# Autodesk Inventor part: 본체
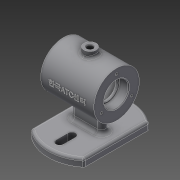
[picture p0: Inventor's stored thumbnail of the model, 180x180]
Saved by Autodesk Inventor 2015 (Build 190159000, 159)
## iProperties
Created: 2017-12
Part Number: 본체
Material: 일반
Document SubType Name: Modeling
Designer: SCD-A05
Density: 1 g/cm^3
Appearance: 기본값
Author: SCD-A05
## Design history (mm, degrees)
sketch "스케치1"
  geometry: L1 (-35, -42.426)-(-35, 42.426); L2 (35, 42.426)-(35, -42.426); A1 r 55 centre (0, 0) between (35, 42.426) and (-35, 42.426); A2 r 55 centre (0, 0) between (-35, -42.426) and (35, -42.426); 1 further point
  constraints: 4 end point, 4 point on circle, 2 centre point, 1 coincident, 1 parallel, 1 vertical
  dimensions: "d1" = 70 distance between parallel lines of L1 L2; "d2" = 35 distance from line of point (0, 0) L1; "d3" = 55 radius of A1; "d4" = 55 radius of A2
extrude "돌출1" new body sketch "스케치1" distance "d5" = 10; taper "d6" = 0 deg
sketch "스케치2"
  geometry: L1 (-15, -5)-(15, -5); L2 (15, 5)-(-15, 5); A1 r 55 centre (0, 0) between (-35, -42.426) and (35, -42.426) reference; A2 r 5 centre (-15, 0) between (-15, 5) and (-20, 0); A3 r 5 centre (-15, 0) between (-20, 0) and (-15, -5); A4 r 5 centre (15, 0) between (20, 0) and (15, 5); A5 r 5 centre (15, 0) between (15, -5) and (20, 0); 2 further points
  constraints: 8 point on circle, 4 centre point, 4 end point, 4 tangent, 2 concentric, 2 horizontal, 2 point on line, 1 parallel, 12 other
  dimensions: "d9" = 5 radius of A2; "d10" = 5 radius of A4; "d11" = 30 distance of A2.centre A4.centre; "d13" = 15 distance of A2.centre A1.centre; "d14" = 0 vertical distance of A1.centre A5.centre; "d15" = 10 distance between parallel lines of L2 L1
extrude "돌출2" join sketch "스케치2" distance "d16" = 52; taper "d17" = 0 deg
node "작업 평면1"
sketch "스케치5"
  geometry: L1 (-20, -10)-(-20, 0) reference; L2 (-20, 0)-(-5, 0) reference; L3 (-5, 0)-(-5, 52) reference; L4 (-5, 52)-(35, 52) reference; L5 (35, 52)-(35, 0) reference; L6 (35, 0)-(50, 0) reference; L7 (50, 0)-(50, -10) reference; L8 (50, -10)-(-20, -10) reference; L9 (-20, 82)-(50, 82); L10 (50, 82)-(50, 52); L11 (-20, 82)-(-20, 52); L12 (-20, 52)-(-5, 52); L13 (35, 52)-(50, 52); 1 further point
  constraints: 11 end point, 2 horizontal, 2 vertical, 1 collinear, 1 perpendicular
  dimensions: "d18" = 70 distance of L9.start L9.end; "d19" = 30 distance of L9.end L10.end; "d20" = 35 distance from line of point (15, -10) L11
revolve "회전1" sketch "스케치5" stored, may be unused: angle "d21" = 90 deg
sketch "스케치6"
  geometry: C1 r 30 at (0, 0) reference; C2 r 16 at (0, 0); 1 further point
  constraints: 1 centre point, 1 coincident
  dimensions: "d22" = 32 diameter of C2
extrude "돌출3" cut sketch "스케치6" distance "d23" = 12; taper "d24" = 0 deg
sketch "스케치7"
  geometry: C1 r 30 at (0, 0) reference; C2 r 16 at (0, 0); 1 further point
  constraints: 1 centre point, 1 coincident
  dimensions: "d25" = 32 diameter of C2
extrude "돌출4" cut sketch "스케치7" distance "d26" = 12; taper "d27" = 0 deg
node "작업 평면3"
sketch "스케치8"
  geometry: L1 (-52, -51.235)-(-62, -51.235) reference; L2 (-62, -51.235)-(-62, 51.235) reference; L3 (-62, 51.235)-(-52, 51.235) reference; L4 (-52, 51.235)-(-52, 0) reference; L5 (-52, 0)-(-52, -51.235) reference; L6 (-52, 0)-(-30, 0) reference; C1 r 25 at (0, 0); 2 further points
  constraints: 1 centre point, 1 coincident, 1 horizontal alignment
  dimensions: "d29" = 50 diameter of C1
extrude "돌출5" cut sketch "스케치8" distance "d30" = 40; taper "d31" = 0 deg
sketch "스케치9"
  geometry: C1 r 16 at (0, 0) reference; C2 r 14 at (0, 0); 1 further point
  constraints: 1 centre point, 1 coincident
  dimensions: "d32" = 28 diameter of C2
extrude "돌출6" cut sketch "스케치9" distance "d33" = 400; taper "d34" = 0 deg
sketch "스케치10"
  geometry: C1 r 16 at (0, 0) reference; 2 further points
  constraints: 1 horizontal alignment
  dimensions: "d35" = 23 distance of C1.centre point (-23, 0)
hole "구멍1" sketch "스케치10" at (-23, 0) diameter "d36" = 3.242; stored, may be unused: countersink angle "d40" = 90 deg, drill point angle "d42" = 118 deg; dims "d37" = 8, "d38" = 4, "d39" = 2, "d41" = 10
node "작업 평면4"
sketch "스케치11"
  geometry: L1 (15, -5)-(-15, -5) reference; L2 (-15, 5)-(15, 5) reference; L3 (35, 42.426)-(35, -42.426) reference; L4 (-35, -42.426)-(-35, 42.426) reference; L5 (-5, 24)-(-5, 24); L6 (5, 24)-(5, 40); L7 (-5, 40)-(-5, 40); L8 (-5, 40)-(-5, 24); L9 (-5, -40)-(-5, -24); L10 (5, -24)-(5, -40); A1 r 55 centre (0, 0) between (-35, -42.426) and (35, -42.426) reference; A2 r 5 centre (-15, 0) between (-15, 5) and (-15, -5) reference; A3 r 5 centre (15, 0) between (15, -5) and (15, 5) reference; A4 r 55 centre (0, 0) between (35, 42.426) and (-35, 42.426) reference; A5 r 55 centre (0, 0) between (-35, -42.426) and (35, -42.426) reference; A6 r 5 centre (0, 40) between (5, 40) and (-5, 40); A7 r 5 centre (0, 24) between (-5, 24) and (5, 24); A8 r 5 centre (0, -40) between (-5, -40) and (5, -40); A9 r 5 centre (0, -24) between (5, -24) and (-5, -24)
  constraints: 12 end point, 8 point on circle, 4 centre point, 4 vertical alignment, 2 parallel, 2 point on line, 2 vertical, 1 horizontal, 1 perpendicular, 1 tangent
  dimensions: "d46" = 10 distance of L6.end L7.end; "d49" = 16 distance of L7.end L5.start; "d55" = 24 distance of A1.centre A7.centre; "d56" = 5 radius of A7; "d60" = 5 radius of A8; "d61" = 10 diameter of A9; "d62" = 10 distance between parallel lines of L10 L9; "d63" = 24 distance of A1.centre A9.centre; "d64" = 16 distance of L9.start L9.end
extrude "돌출7" cut sketch "스케치11" distance "d65" = 400; taper "d66" = 0 deg
node "작업 평면5"
sketch "스케치12"
  geometry: L1 (-35, -30)-(-35, 30) reference; L2 (-35, 30)-(35, 30) reference; 2 further points
  constraints: 1 other
  dimensions: "d67" = 35 distance from line of L1 point (0, 0); "d68" = 30 distance from line of L2 point (0, 0)
feature "엠보싱1" sketch "스케치12" dims "d1" = 70, "d2" = 35, "d3" = 55, "d4" = 55, "d9" = 5, "d10" = 5, "d11" = 30, "d13" = 15, "d14" = 0, "d15" = 10, "d69" = 0.5, "d70" = 0
node "작업 평면6"
sketch "스케치13"
  geometry: C1 r 8 at (0, 0); 1 further point
  constraints: 1 centre point, 1 coincident
  dimensions: "d71" = 16 diameter of C1
extrude "돌출8" join sketch "스케치13" stored distance "d72" = 14; taper "d73" = 0 deg
sketch "스케치14"
  geometry: C1 r 8 at (0, 0) reference; C2 r 4 at (0, 0)
  constraints: 1 centre point, 1 coincident
  dimensions: "d74" = 8 diameter of C2
extrude "돌출9" cut sketch "스케치14" distance "d75" = 14; taper "d76" = 0 deg
sketch "스케치15"
  geometry: L1 (35, 78)-(23, 78) reference; L2 (23, 78)-(23, 76) reference; L3 (23, 76)-(20, 76) reference; L4 (20, 76)-(20, 87) reference; L5 (20, 87)-(8, 87) reference; L6 (8, 87)-(8, 85) reference; L7 (8, 85)-(4, 85) reference; L8 (4, 85)-(4, 99) reference; L9 (4, 99)-(8, 99) reference; L10 (8, 99)-(8, 92) reference; L11 (8, 92)-(35, 92) reference; L12 (35, 92)-(35, 86.621) reference; L13 (35, 86.621)-(25, 86.621) reference; L14 (25, 86.621)-(24.026, 85) reference; L15 (24.026, 85)-(25, 83.379) reference; L16 (25, 83.379)-(35, 83.379) reference; L17 (35, 83.379)-(35, 78) reference; L18 (-23, 78)-(-35, 78) reference; L19 (-35, 78)-(-35, 83.379) reference; L20 (-35, 83.379)-(-25, 83.379) reference; L21 (-25, 83.379)-(-24.026, 85) reference; L22 (-24.026, 85)-(-25, 86.621) reference; L23 (-25, 86.621)-(-35, 86.621) reference; L24 (-35, 86.621)-(-35, 92) reference; L25 (-35, 92)-(-8, 92) reference; L26 (-8, 92)-(-8, 99) reference; L27 (-8, 99)-(-4, 99) reference; L28 (-4, 99)-(-4, 85) reference; L29 (-4, 85)-(-8, 85) reference; L30 (-8, 85)-(-8, 87) reference; L31 (-8, 87)-(-20, 87) reference; L32 (-20, 87)-(-20, 76) reference; L33 (-20, 76)-(-23, 76) reference; L34 (-23, 76)-(-23, 78) reference; L35 (35, 10)-(35, 0) reference; L36 (35, 0)-(-35, 0) reference; L37 (-35, 0)-(-35, 10) reference; L38 (-35, 10)-(-20, 10) reference; L39 (-20, 10)-(-20, 32) reference; L40 (-20, 32)-(-35, 32) reference; L41 (-35, 32)-(-35, 46) reference; L42 (-35, 46)-(-23, 46) reference; L43 (-23, 46)-(-23, 48) reference; L44 (-23, 48)-(-20, 48) reference; L45 (-20, 48)-(-20, 37) reference; L46 (-20, 37)-(20, 37) reference; L47 (20, 37)-(20, 48) reference; L48 (20, 48)-(23, 48) reference; L49 (23, 48)-(23, 46) reference; L50 (23, 46)-(35, 46) reference; L51 (35, 46)-(35, 32) reference; L52 (35, 32)-(20, 32) reference; L53 (20, 32)-(20, 10) reference; L54 (20, 10)-(35, 10) reference; L55 (35, 78)-(35, 46) reference; L56 (-35, 46)-(-35, 78) reference; L57 (-35, 62)-(35, 62); L58 (-8, 87)-(8, 87); 1 further point
  constraints: 4 end point, 2 midpoint, 1 collinear
revolve "회전2" sketch "스케치15" stored, may be unused: angle "d77" = 90 deg
chamfer "모따기1" distance "d78" = 1; stored, may be unused: second distance "d79" = 2, angle "d80" = 45 deg
fillet "모깎기1" dims "d81" = 5
fillet "모깎기2" dims "d82" = 3
fillet "모깎기3" dims "d83" = 3
fillet "모깎기4" dims "d84" = 3
chamfer "모따기2" distance "d85" = 1; stored, may be unused: second distance "d86" = 2, angle "d87" = 45 deg
fillet "모깎기5" dims "d88" = 3
fillet "모깎기6" dims "d89" = 0.3
fillet "모깎기7" dims "d90" = 5
node "솔리드1"
pattern_circular "원형 패턴1" dims angle "d44" = 360 deg
mirror "대칭1"
node "절단 모서리 투영2"
node "절단 모서리 투영3"
node "절단 모서리 투영4"
node "절단 모서리 투영5"
other parameters: "d28" = -3
